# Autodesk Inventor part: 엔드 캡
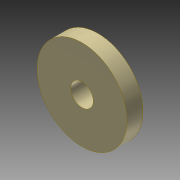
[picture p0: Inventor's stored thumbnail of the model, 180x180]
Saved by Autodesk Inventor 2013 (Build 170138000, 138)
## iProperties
Created: 2024-01
Part Number: 엔드 캡
Material: 강철, 연강
Document SubType Name: Modeling
Designer: mdu-01
Density: 1 g/cm^3
Author: mdu-01
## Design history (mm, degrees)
sketch "스케치1"
  geometry: C1 r 9 at (0, 0); 1 further point
  constraints: 1 centre point, 1 coincident
  dimensions: "d0" = 18 diameter of C1
extrude "돌출1" new body sketch "스케치1" distance "d1" = 3.2; taper "d2" = 0 deg
hole "구멍1" diameter "d5" = 4.5; stored, may be unused: countersink angle "d9" = 90 deg, drill point angle "d11" = 118 deg; dims "d3" = 10, "d4" = 10, "d6" = 6, "d7" = 9.4, "d8" = 2, "d10" = 8
node "솔리드1"
